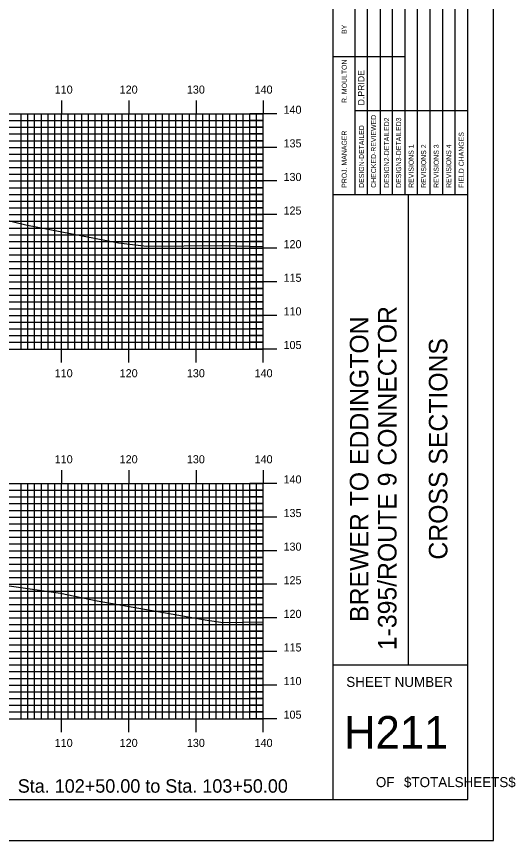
# Model space of a CAD drawing. Extents: x 1767300 to 1767643, y 442591 to 442811.
# Drawn here: x 1767569.2 to 1767643.4, y 442590.5 to 442713.1 of the extents above; entities that cross this region are included whole.
import ezdxf

# ---------------------------------------------------------------- set-up
doc = ezdxf.new("R2010")
doc.units = 0
for name, color, linetype in [('BORDER', 7, 'Continuous'), ('H_V ANNOTATION', 7, 'Continuous'), ('MAJOR', 7, 'Continuous'), ('MINOR', 7, 'Continuous'), ('PLOT BOUNDARY', 7, 'Continuous'), ('S_Roadway_Centerline', 7, 'Continuous')]:
    doc.layers.add(name, color=color, linetype=linetype)

msp = doc.modelspace()

# ---------------------------------------------------------------- linework, layer by layer
at = {"layer": 'BORDER'}
for p, q in [((1767616.34, 442596.67), (1767616.34, 442806.67)), ((1767616.34, 442686.67), (1767636.34, 442686.67)), ((1767627.52, 442616.67), (1767627.52, 442686.67)), ((1767616.34, 442616.67), (1767636.34, 442616.67))]:
    msp.add_line(p, q, dxfattribs=at)
msp.add_lwpolyline([(1767316.34, 442596.67), (1767636.34, 442596.67), (1767636.34, 442806.67), (1767316.34, 442806.67)], close=True, dxfattribs=at)
for points in [[(1767621.43, 442686.68), (1767621.43, 442721.67)], [(1767623.29, 442721.67), (1767623.29, 442686.68)], [(1767625.16, 442686.68), (1767625.16, 442721.67)], [(1767627.02, 442686.68), (1767627.02, 442721.67)], [(1767628.88, 442686.68), (1767628.88, 442721.67)], [(1767630.75, 442686.68), (1767630.75, 442721.67)], [(1767632.61, 442686.68), (1767632.61, 442721.67)], [(1767634.47, 442686.68), (1767634.47, 442721.67)], [(1767619.57, 442686.68), (1767619.57, 442720.26)], [(1767616.34, 442707.17), (1767619.57, 442707.17)], [(1767619.57, 442707.17), (1767627.02, 442707.17)], [(1767619.57, 442699.17), (1767636.34, 442699.17)]]:
    msp.add_lwpolyline(points, dxfattribs=at)
at = {"layer": 'MAJOR'}
for p, q in [((1767575.94, 442700.67), (1767575.94, 442698.67)), ((1767585.94, 442700.67), (1767585.94, 442698.67)), ((1767595.94, 442700.67), (1767595.94, 442698.67)), ((1767605.94, 442700.67), (1767605.94, 442698.67)), ((1767325.94, 442698.67), (1767605.94, 442698.67)), ((1767325.94, 442698.67), (1767605.94, 442698.67)), ((1767575.94, 442663.67), (1767575.94, 442698.67)), ((1767585.94, 442663.67), (1767585.94, 442698.67)), ((1767595.94, 442663.67), (1767595.94, 442698.67)), ((1767607.94, 442698.67), (1767603.93, 442698.67)), ((1767605.94, 442663.67), (1767605.94, 442698.67)), ((1767605.94, 442663.67), (1767605.94, 442698.67)), ((1767325.94, 442693.67), (1767605.94, 442693.67)), ((1767607.94, 442693.67), (1767603.93, 442693.67)), ((1767325.94, 442688.67), (1767605.94, 442688.67)), ((1767607.94, 442688.67), (1767603.93, 442688.67)), ((1767325.94, 442683.67), (1767605.94, 442683.67)), ((1767607.94, 442683.67), (1767603.93, 442683.67)), ((1767325.94, 442678.67), (1767605.94, 442678.67)), ((1767607.94, 442678.67), (1767603.93, 442678.67)), ((1767325.94, 442673.67), (1767605.94, 442673.67)), ((1767607.94, 442673.67), (1767603.93, 442673.67)), ((1767325.94, 442668.67), (1767605.94, 442668.67)), ((1767607.94, 442668.67), (1767603.93, 442668.67)), ((1767325.94, 442663.67), (1767605.94, 442663.67)), ((1767325.94, 442663.67), (1767605.94, 442663.67)), ((1767575.94, 442661.66), (1767575.94, 442663.67)), ((1767585.94, 442661.66), (1767585.94, 442663.67)), ((1767595.94, 442661.66), (1767595.94, 442663.67)), ((1767607.94, 442663.67), (1767603.93, 442663.67)), ((1767605.94, 442661.66), (1767605.94, 442663.67)), ((1767575.94, 442645.67), (1767575.94, 442643.67)), ((1767585.94, 442645.67), (1767585.94, 442643.67)), ((1767595.94, 442645.67), (1767595.94, 442643.67)), ((1767605.94, 442645.67), (1767605.94, 442643.67)), ((1767325.94, 442643.67), (1767605.94, 442643.67)), ((1767325.94, 442643.67), (1767605.94, 442643.67)), ((1767575.94, 442608.67), (1767575.94, 442643.67)), ((1767585.94, 442608.67), (1767585.94, 442643.67)), ((1767595.94, 442608.67), (1767595.94, 442643.67)), ((1767607.94, 442643.67), (1767603.93, 442643.67)), ((1767605.94, 442608.67), (1767605.94, 442643.67)), ((1767605.94, 442608.67), (1767605.94, 442643.67)), ((1767325.94, 442638.67), (1767605.94, 442638.67)), ((1767607.94, 442638.67), (1767603.93, 442638.67)), ((1767325.94, 442633.67), (1767605.94, 442633.67)), ((1767607.94, 442633.67), (1767603.93, 442633.67)), ((1767325.94, 442628.67), (1767605.94, 442628.67)), ((1767607.94, 442628.67), (1767603.93, 442628.67)), ((1767325.94, 442623.67), (1767605.94, 442623.67)), ((1767607.94, 442623.67), (1767603.93, 442623.67)), ((1767325.94, 442618.67), (1767605.94, 442618.67)), ((1767607.94, 442618.67), (1767603.93, 442618.67)), ((1767325.94, 442613.67), (1767605.94, 442613.67)), ((1767607.94, 442613.67), (1767603.93, 442613.67)), ((1767325.94, 442608.67), (1767605.94, 442608.67)), ((1767325.94, 442608.67), (1767605.94, 442608.67)), ((1767575.94, 442606.66), (1767575.94, 442608.67)), ((1767585.94, 442606.66), (1767585.94, 442608.67)), ((1767595.94, 442606.66), (1767595.94, 442608.67)), ((1767607.94, 442608.67), (1767603.93, 442608.67)), ((1767605.94, 442606.66), (1767605.94, 442608.67))]:
    msp.add_line(p, q, dxfattribs=at)
at = {"layer": 'MINOR'}
for p, q in [((1767569.94, 442663.67), (1767569.94, 442698.67)), ((1767570.94, 442663.67), (1767570.94, 442698.67)), ((1767571.94, 442663.67), (1767571.94, 442698.67)), ((1767572.94, 442663.67), (1767572.94, 442698.67)), ((1767573.94, 442663.67), (1767573.94, 442698.67)), ((1767574.94, 442663.67), (1767574.94, 442698.67)), ((1767576.94, 442663.67), (1767576.94, 442698.67)), ((1767577.94, 442663.67), (1767577.94, 442698.67)), ((1767578.94, 442663.67), (1767578.94, 442698.67)), ((1767579.94, 442663.67), (1767579.94, 442698.67)), ((1767580.94, 442663.67), (1767580.94, 442698.67)), ((1767581.94, 442663.67), (1767581.94, 442698.67)), ((1767582.94, 442663.67), (1767582.94, 442698.67)), ((1767583.94, 442663.67), (1767583.94, 442698.67)), ((1767584.94, 442663.67), (1767584.94, 442698.67)), ((1767586.94, 442663.67), (1767586.94, 442698.67)), ((1767587.94, 442663.67), (1767587.94, 442698.67)), ((1767588.94, 442663.67), (1767588.94, 442698.67)), ((1767589.94, 442663.67), (1767589.94, 442698.67)), ((1767590.94, 442663.67), (1767590.94, 442698.67)), ((1767591.94, 442663.67), (1767591.94, 442698.67)), ((1767592.94, 442663.67), (1767592.94, 442698.67)), ((1767593.94, 442663.67), (1767593.94, 442698.67)), ((1767594.94, 442663.67), (1767594.94, 442698.67)), ((1767596.94, 442663.67), (1767596.94, 442698.67)), ((1767597.94, 442663.67), (1767597.94, 442698.67)), ((1767598.94, 442663.67), (1767598.94, 442698.67)), ((1767599.94, 442663.67), (1767599.94, 442698.67)), ((1767600.94, 442663.67), (1767600.94, 442698.67)), ((1767601.94, 442663.67), (1767601.94, 442698.67)), ((1767602.94, 442663.67), (1767602.94, 442698.67)), ((1767603.94, 442663.67), (1767603.94, 442698.67)), ((1767604.94, 442663.67), (1767604.94, 442698.67)), ((1767325.94, 442697.67), (1767605.94, 442697.67)), ((1767325.94, 442696.67), (1767605.94, 442696.67)), ((1767605.94, 442697.67), (1767603.93, 442697.67)), ((1767605.94, 442696.67), (1767603.93, 442696.67)), ((1767325.94, 442695.67), (1767605.94, 442695.67)), ((1767605.94, 442695.67), (1767603.93, 442695.67)), ((1767325.94, 442694.67), (1767605.94, 442694.67)), ((1767605.94, 442694.67), (1767603.93, 442694.67)), ((1767325.94, 442692.67), (1767605.94, 442692.67)), ((1767605.94, 442692.67), (1767603.93, 442692.67)), ((1767325.94, 442691.67), (1767605.94, 442691.67)), ((1767325.94, 442690.67), (1767605.94, 442690.67)), ((1767605.94, 442691.67), (1767603.93, 442691.67)), ((1767605.94, 442690.67), (1767603.93, 442690.67)), ((1767325.94, 442689.67), (1767605.94, 442689.67)), ((1767605.94, 442689.67), (1767603.93, 442689.67)), ((1767325.94, 442687.67), (1767605.94, 442687.67)), ((1767605.94, 442687.67), (1767603.93, 442687.67)), ((1767325.94, 442686.67), (1767605.94, 442686.67)), ((1767325.94, 442685.67), (1767605.94, 442685.67)), ((1767605.94, 442686.67), (1767603.93, 442686.67)), ((1767605.94, 442685.67), (1767603.93, 442685.67)), ((1767325.94, 442684.67), (1767605.94, 442684.67)), ((1767605.94, 442684.67), (1767603.93, 442684.67)), ((1767325.94, 442682.67), (1767605.94, 442682.67)), ((1767605.94, 442682.67), (1767603.93, 442682.67)), ((1767325.94, 442681.67), (1767605.94, 442681.67)), ((1767605.94, 442681.67), (1767603.93, 442681.67)), ((1767325.94, 442680.67), (1767605.94, 442680.67)), ((1767325.94, 442679.67), (1767605.94, 442679.67)), ((1767605.94, 442680.67), (1767603.93, 442680.67)), ((1767605.94, 442679.67), (1767603.93, 442679.67)), ((1767325.94, 442677.67), (1767605.94, 442677.67)), ((1767605.94, 442677.67), (1767603.93, 442677.67)), ((1767325.94, 442676.67), (1767605.94, 442676.67)), ((1767605.94, 442676.67), (1767603.93, 442676.67)), ((1767325.94, 442675.67), (1767605.94, 442675.67)), ((1767325.94, 442674.67), (1767605.94, 442674.67)), ((1767605.94, 442675.67), (1767603.93, 442675.67)), ((1767605.94, 442674.67), (1767603.93, 442674.67)), ((1767325.94, 442672.67), (1767605.94, 442672.67)), ((1767605.94, 442672.67), (1767603.93, 442672.67)), ((1767325.94, 442671.67), (1767605.94, 442671.67)), ((1767605.94, 442671.67), (1767603.93, 442671.67)), ((1767325.94, 442670.67), (1767605.94, 442670.67)), ((1767325.94, 442669.67), (1767605.94, 442669.67)), ((1767605.94, 442670.67), (1767603.93, 442670.67)), ((1767605.94, 442669.67), (1767603.93, 442669.67)), ((1767325.94, 442667.67), (1767605.94, 442667.67)), ((1767605.94, 442667.67), (1767603.93, 442667.67)), ((1767325.94, 442666.67), (1767605.94, 442666.67)), ((1767605.94, 442666.67), (1767603.93, 442666.67)), ((1767325.94, 442665.67), (1767605.94, 442665.67)), ((1767605.94, 442665.67), (1767603.93, 442665.67)), ((1767325.94, 442664.67), (1767605.94, 442664.67)), ((1767605.94, 442664.67), (1767603.93, 442664.67)), ((1767569.94, 442608.67), (1767569.94, 442643.67)), ((1767570.94, 442608.67), (1767570.94, 442643.67)), ((1767571.94, 442608.67), (1767571.94, 442643.67)), ((1767572.94, 442608.67), (1767572.94, 442643.67)), ((1767573.94, 442608.67), (1767573.94, 442643.67)), ((1767574.94, 442608.67), (1767574.94, 442643.67)), ((1767576.94, 442608.67), (1767576.94, 442643.67)), ((1767577.94, 442608.67), (1767577.94, 442643.67)), ((1767578.94, 442608.67), (1767578.94, 442643.67)), ((1767579.94, 442608.67), (1767579.94, 442643.67)), ((1767580.94, 442608.67), (1767580.94, 442643.67)), ((1767581.94, 442608.67), (1767581.94, 442643.67)), ((1767582.94, 442608.67), (1767582.94, 442643.67)), ((1767583.94, 442608.67), (1767583.94, 442643.67)), ((1767584.94, 442608.67), (1767584.94, 442643.67)), ((1767586.94, 442608.67), (1767586.94, 442643.67)), ((1767587.94, 442608.67), (1767587.94, 442643.67)), ((1767588.94, 442608.67), (1767588.94, 442643.67)), ((1767589.94, 442608.67), (1767589.94, 442643.67)), ((1767590.94, 442608.67), (1767590.94, 442643.67)), ((1767591.94, 442608.67), (1767591.94, 442643.67)), ((1767592.94, 442608.67), (1767592.94, 442643.67)), ((1767593.94, 442608.67), (1767593.94, 442643.67)), ((1767594.94, 442608.67), (1767594.94, 442643.67)), ((1767596.94, 442608.67), (1767596.94, 442643.67)), ((1767597.94, 442608.67), (1767597.94, 442643.67)), ((1767598.94, 442608.67), (1767598.94, 442643.67)), ((1767599.94, 442608.67), (1767599.94, 442643.67)), ((1767600.94, 442608.67), (1767600.94, 442643.67)), ((1767601.94, 442608.67), (1767601.94, 442643.67)), ((1767602.94, 442608.67), (1767602.94, 442643.67)), ((1767603.94, 442608.67), (1767603.94, 442643.67)), ((1767604.94, 442608.67), (1767604.94, 442643.67)), ((1767325.94, 442642.67), (1767605.94, 442642.67)), ((1767325.94, 442641.67), (1767605.94, 442641.67)), ((1767605.94, 442642.67), (1767603.93, 442642.67)), ((1767605.94, 442641.67), (1767603.93, 442641.67)), ((1767325.94, 442640.67), (1767605.94, 442640.67)), ((1767605.94, 442640.67), (1767603.93, 442640.67)), ((1767325.94, 442639.67), (1767605.94, 442639.67)), ((1767605.94, 442639.67), (1767603.93, 442639.67)), ((1767325.94, 442637.67), (1767605.94, 442637.67)), ((1767325.94, 442636.67), (1767605.94, 442636.67)), ((1767605.94, 442637.67), (1767603.93, 442637.67)), ((1767605.94, 442636.67), (1767603.93, 442636.67)), ((1767325.94, 442635.67), (1767605.94, 442635.67)), ((1767605.94, 442635.67), (1767603.93, 442635.67)), ((1767325.94, 442634.67), (1767605.94, 442634.67)), ((1767605.94, 442634.67), (1767603.93, 442634.67)), ((1767325.94, 442632.67), (1767605.94, 442632.67)), ((1767325.94, 442631.67), (1767605.94, 442631.67)), ((1767605.94, 442632.67), (1767603.93, 442632.67)), ((1767605.94, 442631.67), (1767603.93, 442631.67)), ((1767325.94, 442630.67), (1767605.94, 442630.67)), ((1767605.94, 442630.67), (1767603.93, 442630.67)), ((1767325.94, 442629.67), (1767605.94, 442629.67)), ((1767605.94, 442629.67), (1767603.93, 442629.67)), ((1767325.94, 442627.67), (1767605.94, 442627.67)), ((1767605.94, 442627.67), (1767603.93, 442627.67)), ((1767325.94, 442626.67), (1767605.94, 442626.67)), ((1767325.94, 442625.67), (1767605.94, 442625.67)), ((1767605.94, 442626.67), (1767603.93, 442626.67)), ((1767605.94, 442625.67), (1767603.93, 442625.67)), ((1767325.94, 442624.67), (1767605.94, 442624.67)), ((1767605.94, 442624.67), (1767603.93, 442624.67)), ((1767325.94, 442622.67), (1767605.94, 442622.67)), ((1767605.94, 442622.67), (1767603.93, 442622.67)), ((1767325.94, 442621.67), (1767605.94, 442621.67)), ((1767325.94, 442620.67), (1767605.94, 442620.67)), ((1767605.94, 442621.67), (1767603.93, 442621.67)), ((1767605.94, 442620.67), (1767603.93, 442620.67)), ((1767325.94, 442619.67), (1767605.94, 442619.67)), ((1767605.94, 442619.67), (1767603.93, 442619.67)), ((1767325.94, 442617.67), (1767605.94, 442617.67)), ((1767605.94, 442617.67), (1767603.93, 442617.67)), ((1767325.94, 442616.67), (1767605.94, 442616.67)), ((1767605.94, 442616.67), (1767603.93, 442616.67)), ((1767325.94, 442615.67), (1767605.94, 442615.67)), ((1767325.94, 442614.67), (1767605.94, 442614.67)), ((1767605.94, 442615.67), (1767603.93, 442615.67)), ((1767605.94, 442614.67), (1767603.93, 442614.67)), ((1767325.94, 442612.67), (1767605.94, 442612.67)), ((1767605.94, 442612.67), (1767603.93, 442612.67)), ((1767325.94, 442611.67), (1767605.94, 442611.67)), ((1767605.94, 442611.67), (1767603.93, 442611.67)), ((1767325.94, 442610.67), (1767605.94, 442610.67)), ((1767325.94, 442609.67), (1767605.94, 442609.67)), ((1767605.94, 442610.67), (1767603.93, 442610.67)), ((1767605.94, 442609.67), (1767603.93, 442609.67))]:
    msp.add_line(p, q, dxfattribs=at)
at = {"layer": 'PLOT BOUNDARY'}
msp.add_lwpolyline([(1767300.15, 442590.55), (1767640.15, 442590.55), (1767640.15, 442810.55), (1767300.15, 442810.55)], close=True, dxfattribs=at)
at = {"layer": 'S_Roadway_Centerline'}
for points in [[(1767492.19, 442687.95), (1767503.68, 442687.68), (1767503.89, 442687.68), (1767504.02, 442687.68), (1767515.87, 442687.45), (1767523.31, 442687.33), (1767528.58, 442687.2), (1767535.45, 442686.9), (1767549.54, 442686.24), (1767552.23, 442686.02), (1767555.19, 442685.4), (1767564.66, 442683.6), (1767570.63, 442682.14), (1767584.43, 442679.45), (1767588.56, 442678.95), (1767599.71, 442679.05), (1767605.94, 442678.92)], [(1767484.67, 442631.49), (1767502.67, 442631.45), (1767503.67, 442631.45), (1767515.91, 442631.58), (1767523.45, 442631.58), (1767534.8, 442631.42), (1767539.36, 442631.33), (1767541.96, 442631.26), (1767552.26, 442630.26), (1767562.01, 442629.38), (1767568.14, 442628.43), (1767575.79, 442627.34), (1767581.25, 442626.23), (1767597.6, 442623.32), (1767599.97, 442623), (1767605.94, 442623.06)]]:
    msp.add_lwpolyline(points, dxfattribs=at)

# ---------------------------------------------------------------- texts
at = {"layer": 'BORDER'}
for s, height, p in [('BY', 0.743, (1767618.34, 442710.54)), ('R. MOULTON', 0.745, (1767618.35, 442700.28)), ('D.PRIDE', 0.969, (1767620.98, 442699.92)), ('CHECKED-REVIEWED', 0.7455, (1767622.7, 442687.65)), ('DESIGN-DETAILED', 0.7455, (1767620.91, 442687.65)), ('DESIGN2-DETAILED2', 0.7455, (1767624.64, 442687.65)), ('DESIGN3-DETAILED3', 0.7455, (1767626.43, 442687.65)), ('PROJ. MANAGER', 0.7455, (1767618.34, 442687.65)), ('FIELD CHANGES', 0.7455, (1767635.74, 442687.65)), ('REVISIONS 1', 0.7455, (1767628.29, 442687.65)), ('REVISIONS 2', 0.7455, (1767630.15, 442687.65)), ('REVISIONS 3', 0.7455, (1767632.02, 442687.65)), ('REVISIONS 4', 0.7455, (1767633.88, 442687.65)), ('1-395/ROUTE 9 CONNECTOR', 2.7557, (1767625.74, 442618.87)), ('BREWER TO EDDINGTON', 2.7557, (1767621.56, 442623.07)), ('CROSS SECTIONS', 2.7557, (1767633.31, 442632.34))]:
    msp.add_text(s, height=height, rotation=90, dxfattribs=at).set_placement(p)
for s, height, p in [('SHEET NUMBER', 1.4905, (1767618.27, 442613.4)), ('H211', 4.839, (1767617.96, 442604.23)), ('OF', 1.491, (1767622.67, 442598.49)), ('$TOTALSHEETS$', 1.4905, (1767626.85, 442598.49))]:
    msp.add_text(s, height=height, dxfattribs=at).set_placement(p)
at = {"layer": 'H_V ANNOTATION'}
for s, height, p in [('110', 1.2, (1767574.92, 442701.67)), ('120', 1.2, (1767584.58, 442701.67)), ('130', 1.2, (1767594.57, 442701.67)), ('140', 1.2, (1767604.64, 442701.67)), ('140', 1.2, (1767608.94, 442698.67)), ('135', 1.2, (1767608.94, 442693.67)), ('130', 1.2, (1767608.94, 442688.67)), ('125', 1.2, (1767608.94, 442683.67)), ('120', 1.2, (1767608.94, 442678.67)), ('115', 1.2, (1767608.94, 442673.67)), ('110', 1.2, (1767608.94, 442668.67)), ('105', 1.2, (1767608.94, 442663.67)), ('110', 1.2, (1767574.92, 442659.47)), ('120', 1.2, (1767584.58, 442659.47)), ('130', 1.2, (1767594.57, 442659.47)), ('140', 1.2, (1767604.64, 442659.47)), ('110', 1.2, (1767574.92, 442646.67)), ('120', 1.2, (1767584.58, 442646.67)), ('130', 1.2, (1767594.57, 442646.67)), ('140', 1.2, (1767604.64, 442646.67)), ('140', 1.2, (1767608.94, 442643.67)), ('135', 1.2, (1767608.94, 442638.67)), ('130', 1.2, (1767608.94, 442633.67)), ('125', 1.2, (1767608.94, 442628.67)), ('120', 1.2, (1767608.94, 442623.67)), ('115', 1.2, (1767608.94, 442618.67)), ('110', 1.2, (1767608.94, 442613.67)), ('105', 1.2, (1767608.94, 442608.67)), ('110', 1.2, (1767574.92, 442604.47)), ('120', 1.2, (1767584.58, 442604.47)), ('130', 1.2, (1767594.57, 442604.47)), ('140', 1.2, (1767604.64, 442604.47)), ('Sta. 102+50.00 to Sta. 103+50.00', 2.0004, (1767569.43, 442597.66))]:
    msp.add_text(s, height=height, dxfattribs=at).set_placement(p)

doc.saveas('drawing.dxf')
